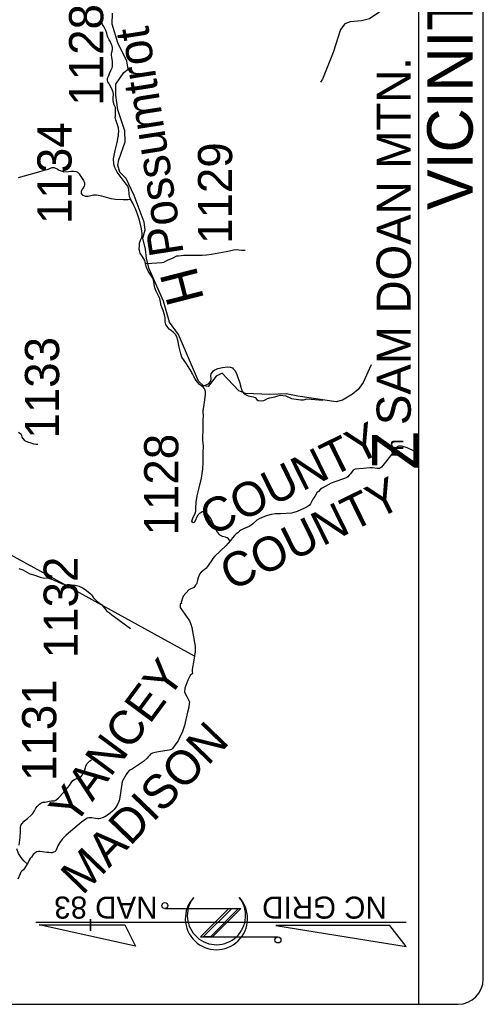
# Model space of a CAD drawing. Extents: x 264770 to 739672, y 157173 to 249791.
# Drawn here: x 727650 to 728336, y 157173 to 158631 of the extents above; entities that cross this region are included whole.
import ezdxf

# ---------------------------------------------------------------- set-up
doc = ezdxf.new("R2010")
doc.units = 0
for name, color, linetype in [('Old_Level_27', 7, 'Continuous'), ('Old_Level_5', 7, 'Continuous'), ('Prop Cable Guiderail Anchor Unit CELL', 7, 'Continuous'), ('Prop Cable Guiderail Single Face', 7, 'Continuous'), ('Prop Dimension', 7, 'Continuous'), ('Prop GRAU 350 Approach CELL', 7, 'Continuous'), ('Prop GRAU M350 Trailing CELL', 7, 'Continuous'), ('Prop Guardrail Anchor Unit CELL', 7, 'Continuous'), ('Prop Lane Arrow Right Turn CELL', 7, 'Continuous'), ('Prop Lane Arrow Shared Lt and Thru CELL', 7, 'Continuous'), ('Prop Structure Anchor Unit CELL', 7, 'Continuous'), ('Prop_centerline', 7, 'Continuous'), ('Scratch_Level_0', 7, 'Continuous'), ('stationing', 7, 'Continuous')]:
    doc.layers.add(name, color=color, linetype=linetype)

msp = doc.modelspace()

# ---------------------------------------------------------------- linework, layer by layer
at = {"layer": 'Old_Level_5'}
for points in [[(728240.9, 158679.5), (728193.4, 158646.2), (728183.1, 158643.1), (728167.9, 158632.5), (728156.2, 158629.4), (728139.4, 158628.3), (728131.5, 158625), (728124.9, 158616.5), (728114.4, 158582.5), (728098.4, 158543.3), (728095.3, 158538.8)], [(728170.6, 158119.7), (728158.6, 158093.8), (728151.3, 158083.6), (728142.9, 158076.3), (728128, 158067.5), (728118.5, 158064.9), (728061.8, 158073.3), (728044.8, 158076.8), (728020.5, 158075.8), (727984.2, 158077.7), (727974.4, 158081.5), (727949.7, 158107.5), (727940.9, 158103.1), (727929.1, 158087.8), (727922.2, 158088.6), (727914.8, 158095.8), (727885.2, 158165.1), (727871.8, 158183.1), (727863, 158214.3), (727841.9, 158262.3), (727837.8, 158277.6), (727836.5, 158291.1), (727832.5, 158307.5), (727835.7, 158319.7), (727834.3, 158331.4), (727819.5, 158371), (727807.4, 158395.9), (727798.4, 158405.6), (727795.4, 158415.6), (727796.7, 158423.7), (727806.4, 158450.2), (727805.8, 158466.6), (727795.2, 158497.8), (727792.4, 158519.5), (727792.5, 158535.8), (727804.1, 158552.9), (727810.8, 158558), (727808.8, 158569.7), (727795.1, 158597), (727786.9, 158624.7), (727787.4, 158641)]]:
    msp.add_lwpolyline(points, dxfattribs=at)
at = {"layer": 'Prop Dimension'}
msp.add_line((727948.2, 157293.8), (727948.2, 157293.8), dxfattribs=at)
at = {"layer": 'Prop GRAU 350 Approach CELL'}
for p, q in [((728240.9, 157172.6), (728240.9, 160226.7)), ((728336.5, 157210.1), (728336.5, 160189.2)), ((726994.9, 157172.6), (728299, 157172.6))]:
    msp.add_line(p, q, dxfattribs=at)
msp.add_arc((728299, 157210.1), 37.5, 270, 360, dxfattribs=at)
at = {"layer": 'Prop Guardrail Anchor Unit CELL'}
msp.add_line((727701.1, 157802.8), (727626.3, 157844), dxfattribs=at)
msp.add_lwpolyline([(727908.8, 157688.5), (727776, 157761.6), (727701.1, 157802.8)], dxfattribs=at)
at = {"layer": 'Prop Lane Arrow Right Turn CELL'}
msp.add_lwpolyline([(727661.1, 157380.5), (727656.8, 157384.6), (727653.8, 157388.1), (727651.1, 157391.7), (727648.3, 157396.2), (727645.6, 157402.7)], dxfattribs=at)
at = {"layer": 'Prop Lane Arrow Shared Lt and Thru CELL'}
for points in [[(727813.9, 158365.6), (727812.6, 158369.5), (727812.3, 158373.4), (727811.5, 158380.1), (727810, 158384.6), (727806.4, 158389.8), (727794.3, 158405.6), (727792, 158410.4), (727791, 158412.3), (727789.6, 158417.3), (727789, 158425.2), (727791.2, 158437.6), (727794.5, 158449.2), (727795.9, 158457.5), (727796.1, 158459.3), (727796.4, 158462.4), (727796.6, 158465.3), (727796.1, 158470.9), (727792.1, 158482.8), (727791.6, 158485), (727791.5, 158486.6), (727791.6, 158488.3), (727791.8, 158491.1), (727791.9, 158494.4), (727791.9, 158498.4), (727791.6, 158501), (727789.9, 158505.1), (727788.7, 158508.8), (727788.3, 158512.2), (727788.3, 158516), (727788.8, 158520.4), (727788.6, 158523.9), (727787.6, 158526.4), (727785.5, 158530.9), (727783.2, 158535.2), (727781.9, 158537.3), (727780.7, 158539), (727780, 158541.3), (727780.1, 158544), (727780.4, 158545.6), (727781.8, 158548.5), (727783.2, 158551.7), (727785.1, 158555.8), (727786.4, 158558.7), (727786.9, 158559.8), (727787.2, 158561.7), (727787.6, 158565.3), (727787.6, 158569.2), (727786.3, 158575.5), (727785.8, 158578.9), (727786, 158581.5), (727786.9, 158584.7), (727787.4, 158587.3), (727787.6, 158590.1), (727787, 158592.5), (727786, 158594.4), (727784.2, 158598.5), (727782.4, 158601.6), (727780.7, 158605.3), (727779.6, 158608.2), (727778.8, 158611.1), (727777.4, 158615.3), (727776.1, 158618.4), (727774.6, 158621.2), (727772.6, 158624.2), (727771.1, 158627.8), (727770.9, 158631), (727771, 158634.3)], [(727648.3, 158397.7), (727678.1, 158406), (727684.8, 158407.8), (727687.9, 158408.6), (727690.7, 158409.2), (727694.7, 158410.8), (727696.5, 158411.8), (727698.1, 158412.3), (727700.6, 158412.3), (727705.4, 158410.4), (727708.6, 158408.5), (727712.9, 158406.7), (727715.5, 158406), (727722.3, 158406.3), (727726.4, 158406.7), (727729.8, 158406.6), (727733.5, 158406.2), (727735.1, 158405.7), (727736.2, 158404.8), (727737.8, 158403.1), (727739.6, 158400.2), (727744.4, 158393), (727744.8, 158391.9), (727745.7, 158389.7), (727745.7, 158386.8), (727745.4, 158384.7), (727743.2, 158380.9), (727741, 158377.2), (727741.1, 158373.9), (727742.5, 158371.7), (727746.9, 158369.9), (727751.2, 158369.9), (727759.4, 158371.6), (727763.9, 158372), (727771.3, 158370.5), (727777.9, 158368.3), (727784.9, 158366.3), (727791.7, 158365.2), (727803, 158364.8), (727810.8, 158365.1), (727813.9, 158365.6)], [(727836.5, 158269.9), (727835.1, 158274.3), (727832.4, 158279.5), (727828.6, 158285.6), (727827.3, 158289.2), (727827.1, 158291), (727827.1, 158292.6), (727827.2, 158295.1), (727827.5, 158300.2), (727828.8, 158304.6), (727830.8, 158308.8), (727831.5, 158311.3), (727831.5, 158314.7), (727830.1, 158321.6), (727827.5, 158334.3), (727824.5, 158343.3), (727821.7, 158350.8), (727818.7, 158356.9), (727817.5, 158359.3), (727813.9, 158365.6)], [(727836.5, 158269.9), (727845.4, 158270.6), (727853.2, 158270.9), (727860.5, 158271.5), (727863.4, 158272.2), (727869, 158274.8), (727877.2, 158278.4), (727882.7, 158281.2), (727885.3, 158281.6), (727892.8, 158282.2), (727904.9, 158282.2), (727920.4, 158282.4), (727926.4, 158282.9), (727933.9, 158284), (727955.8, 158287.7), (727960.8, 158288.7), (727966.6, 158290.1), (727970.7, 158290.6), (727974.7, 158290.3), (727978.2, 158289.8), (727983.8, 158290)], [(727919.5, 158088.5), (727916.1, 158090.6), (727911.5, 158096.7), (727908, 158102.6), (727905.8, 158106.6), (727905.1, 158107.9), (727904.3, 158109.4), (727902.1, 158113.3), (727897.2, 158121.5), (727892.6, 158127.7), (727890.2, 158131.4), (727888.4, 158136), (727886.3, 158146), (727884.2, 158156.7), (727882.5, 158161.2), (727880.7, 158164.7), (727877.1, 158168.4), (727874.6, 158170.3), (727872.7, 158171.6), (727871.5, 158173), (727868.2, 158176.7), (727866.2, 158179.8), (727865.3, 158184), (727865.2, 158189.8), (727864.3, 158194.2), (727862.5, 158200.3), (727859.7, 158207.6), (727858.5, 158213.1), (727857.4, 158218.3), (727855.6, 158222.2), (727851.9, 158229.3), (727850.1, 158234.1), (727849.1, 158239), (727848.5, 158243.6), (727847.2, 158248.1), (727844.1, 158253), (727840.3, 158258.9), (727837.6, 158264.4), (727837.3, 158265.7), (727836.5, 158269.9)], [(727919.5, 158088.5), (727924.8, 158090), (727929.4, 158091.8), (727932.8, 158095.7), (727933.5, 158099.2), (727933, 158104), (727933.6, 158106.6), (727937.2, 158111.1), (727938.9, 158112.3), (727941.2, 158113.7), (727943.6, 158114.7), (727950.5, 158116.1), (727957.7, 158116.9), (727961.6, 158116.7), (727964.9, 158115.4), (727966.3, 158113.9), (727968.5, 158111.5), (727970.8, 158106.9), (727973.2, 158101.3), (727976.1, 158093.2), (727976.9, 158088.5), (727978.2, 158084), (727979.1, 158081.6), (727982.5, 158077), (727988.2, 158073.9), (727990.7, 158073.5), (727995.6, 158072.3), (727998.5, 158071.3), (728000.9, 158068.5), (728003.3, 158067.3), (728007.6, 158066.7), (728011.4, 158067.3), (728013.6, 158068.2), (728016.9, 158070), (728018.7, 158070.5), (728020.4, 158070.9), (728027.6, 158072.3), (728032.2, 158074.1), (728035.6, 158074.8), (728044.3, 158073.9), (728052.7, 158070.1), (728066.2, 158067.9), (728070.4, 158068.1), (728075.6, 158069.8), (728098.7, 158067.8)], [(727961.6, 157858.9), (727960.3, 157860.6), (727959.2, 157862.2), (727957.3, 157863.8), (727954.9, 157864.7), (727950.3, 157865.8), (727947.5, 157866.9), (727946.1, 157868.3), (727942.9, 157871.9), (727937.7, 157882.4), (727932.8, 157892.5), (727928.2, 157898.9), (727926.6, 157900.8), (727924.4, 157901.4), (727922.1, 157902.3), (727920.4, 157902.2), (727915.8, 157899.2), (727913.4, 157896.8), (727908.8, 157887), (727906.9, 157886), (727905.7, 157886.7), (727905, 157888.3), (727905.2, 157889.8), (727906.3, 157892.9), (727909.6, 157900.2), (727910.6, 157903.1), (727910.9, 157908.6), (727911.1, 157916), (727912.8, 157926), (727915.3, 157935.7), (727919, 157952), (727921.2, 157966.1), (727921.7, 157975.6), (727921.8, 157990.8), (727922.1, 157999.3), (727921.4, 158008.2), (727921.4, 158014.2), (727921.5, 158022.4), (727921.8, 158037.3), (727922.3, 158045.4), (727921.8, 158049.4), (727921.8, 158052.5), (727922.8, 158057.6), (727924.2, 158067.9), (727925.2, 158076.5), (727925, 158080.1), (727924.8, 158082.6), (727923.7, 158084.4), (727922, 158086.4), (727919.5, 158088.5)], [(727648.1, 158020.1), (727650, 158018.8), (727651.1, 158017.5), (727652.5, 158015.5), (727653, 158012.8), (727654, 158011.1), (727657.1, 158008), (727661.7, 158005.7), (727666.5, 158004.2), (727670.8, 158002.8), (727673.8, 158002.6), (727676.6, 158002.4)], [(727648.6, 157818.3), (727654.8, 157816), (727664.8, 157810.2), (727672.4, 157808.2), (727680.2, 157805.6), (727684.7, 157804.4), (727692.6, 157803.9), (727698.8, 157801.7), (727705.5, 157799), (727712.7, 157795.3), (727717.3, 157794.4), (727731.9, 157793.6), (727737.9, 157792), (727742.8, 157789.5), (727746.9, 157787.1), (727753.9, 157781.5), (727756.1, 157779.1), (727759.5, 157774.8), (727763.7, 157770.1), (727768, 157767), (727771.4, 157764.2), (727775.8, 157759.5), (727778.4, 157755.6), (727783, 157752.6), (727786.3, 157749.8), (727790, 157747.2), (727814.1, 157729.5)], [(727649.1, 157408.2), (727650.8, 157420.2), (727651.1, 157428.6), (727651.3, 157434.5), (727651.8, 157437.3), (727653.2, 157440.2), (727656.5, 157444), (727662.2, 157448.4), (727666.5, 157452.2), (727669.2, 157455.4), (727671.7, 157459), (727673.9, 157463.2), (727676.5, 157466.3), (727679.2, 157469), (727681.5, 157470.8), (727684.4, 157471.9), (727687.9, 157472.3), (727693.7, 157473.4), (727697.1, 157474), (727701.5, 157474.2), (727703.4, 157475.1), (727707.2, 157478.3), (727715.4, 157487.1), (727721.3, 157493.6), (727723.8, 157496.6), (727726.2, 157500.7), (727728.8, 157504.3), (727731.3, 157505.8), (727734.1, 157506.9), (727737.3, 157507), (727739.4, 157508.3), (727742.5, 157512.2), (727746.3, 157519.8), (727747.9, 157525.2), (727749.4, 157528.6), (727751.6, 157531), (727753.8, 157533.2), (727756.5, 157534.6)]]:
    msp.add_lwpolyline(points, dxfattribs=at)
at = {"layer": 'Prop Structure Anchor Unit CELL'}
for points in [[(728201, 157987.4), (728185.7, 157968.5), (728183, 157966.6), (728179.8, 157966.4), (728172.6, 157967.4), (728168.7, 157967.4), (728159, 157966.6), (728146.7, 157965.4), (728143.7, 157964.1), (728142.1, 157962), (728139.9, 157958.4), (728137.9, 157956.4), (728135.9, 157954.2), (728134.2, 157953.2), (728131.1, 157951.7), (728116.5, 157946.8), (728111.4, 157944.8), (728097.9, 157937.1), (728095.3, 157935.5), (728092.4, 157932.5), (728090, 157930.2), (728087, 157925), (728084.3, 157921), (728080.5, 157914), (728078.7, 157911.6), (728075.8, 157909.4), (728071.7, 157907.7), (728061, 157902.5), (728056, 157901.1), (728052.7, 157900.3), (728036.4, 157899.2), (728029, 157899.2), (728022.4, 157898.3), (728016.8, 157896.9), (728012.3, 157895.4), (728007.9, 157893.3), (728004.8, 157891.7), (728001.3, 157889.7), (727995.4, 157884.6), (727992.6, 157882.2), (727989.8, 157880.3), (727981.2, 157877.1), (727977.6, 157874.9), (727975.5, 157873.3), (727972.8, 157871.1), (727970.7, 157869.4), (727968.1, 157867.1), (727965.3, 157863.8), (727962.3, 157859.7), (727955.3, 157851.9), (727938.9, 157836.7), (727935.9, 157833), (727934.5, 157830.8), (727933.6, 157829), (727930.1, 157824), (727928.3, 157821.4), (727925.6, 157818.2), (727923.3, 157816.1), (727918.6, 157812.6), (727916.2, 157809.9), (727914.5, 157804.6), (727913.2, 157800.9), (727912.2, 157797), (727912.1, 157796.5), (727911.7, 157795.2), (727911, 157794.2), (727910.4, 157793.3), (727908, 157790.1), (727900.4, 157786.8), (727892, 157777), (727889.4, 157769.8), (727889.2, 157768.4), (727889.4, 157766.4), (727887.4, 157765.9), (727887.4, 157760.2), (727901.6, 157740.5), (727903.4, 157735.7), (727904.9, 157730.8), (727906.6, 157722.2), (727910, 157703.4), (727909.8, 157699.2), (727909.9, 157695.4), (727907.8, 157682.5), (727905.5, 157668.5), (727905.5, 157665.5), (727905.8, 157662.5), (727902.6, 157659.5), (727898.8, 157652.6), (727896.2, 157645), (727894.3, 157640.8), (727893.9, 157635.1), (727897.7, 157628.7), (727901.4, 157620.7), (727900.9, 157618.3), (727900.3, 157612.9), (727898.5, 157605.4), (727893.9, 157585.4)], [(728240.9, 157986.5), (728240.8, 157986.6), (728239.9, 157987.5), (728236.5, 157989.9), (728233.1, 157992.4), (728232.2, 157992.8), (728223.9, 157997.2), (728215.8, 157999.6), (728211, 157999.6), (728208.7, 157998.4), (728201, 157987.4)], [(727893.9, 157585.4), (727892.2, 157579.5), (727890.8, 157575.4), (727886.2, 157566.7), (727884.4, 157562.7), (727881.2, 157558.4), (727876.4, 157551.8), (727875, 157550.3), (727873.3, 157549.6), (727871.2, 157549), (727855.5, 157546.8), (727850.4, 157545.8), (727846.6, 157544.6), (727843.7, 157543.1), (727842.1, 157541.4), (727840.4, 157539.2), (727838.9, 157537.3), (727833.2, 157532.4), (727828.8, 157529.2), (727816.8, 157521.6), (727812.3, 157519), (727809.4, 157516.1), (727807.4, 157512.8), (727801.8, 157502.8), (727801.2, 157499.1), (727800.7, 157495.7), (727799.7, 157489.4), (727797.6, 157475.9), (727796.6, 157472.8), (727794.6, 157468.6), (727792.2, 157464.7), (727789.7, 157461.1), (727787.4, 157458.9), (727783.8, 157455.6), (727780, 157453), (727776, 157450.4), (727772, 157448.6), (727769.6, 157447.8), (727767.9, 157447.6), (727765.7, 157447.6), (727762, 157447.7), (727756.9, 157448.9), (727752.4, 157448.9), (727750.1, 157448.4), (727747.8, 157447.1), (727741.5, 157442.3), (727737.8, 157439.6), (727718.6, 157423.2), (727716.8, 157421.3), (727714.9, 157419.4), (727713.4, 157417.8), (727712, 157415.8), (727709.3, 157412.3), (727706.4, 157407.4), (727703.4, 157400), (727702, 157398.5), (727700, 157397.8), (727698.3, 157397.1), (727696.1, 157397.1), (727692.9, 157397.3), (727690, 157397.6), (727680, 157398.8), (727677.9, 157398.8), (727675.5, 157398.3), (727673.1, 157397.1), (727671.9, 157395.9), (727670, 157394.3), (727667.4, 157390.8), (727665.6, 157388.5), (727664.1, 157385.9), (727661.8, 157381.6), (727655.4, 157371.7), (727653.2, 157369.7), (727651.9, 157368.2), (727650.8, 157365.9), (727647.1, 157357.8)]]:
    msp.add_lwpolyline(points, dxfattribs=at)
at = {"layer": 'Prop_centerline'}
for p, q in [((727906.7, 157329.9), (727907.1, 157330.6)), ((727907.1, 157330.6), (727906.7, 157329.9)), ((727864.9, 157314.4), (727977.3, 157314.4)), ((727959.7, 157314.4), (727917.9, 157272.5)), ((727974.2, 157314.4), (727932.4, 157272.5)), ((727974.2, 157314.4), (727932.4, 157272.5)), ((727932.4, 157272.5), (727974.2, 157314.4)), ((727977.3, 157314.4), (727935.4, 157272.5)), ((728222.3, 157293.8), (727673.8, 157293.8)), ((727917.9, 157272.5), (728032.3, 157272.5))]:
    msp.add_line(p, q, dxfattribs=at)
for points in [[(727932.4, 157272.5), (727921.9, 157272.5), (727964.1, 157314.4), (727974.2, 157314.4)], [(727821.3, 157258.7), (727678.9, 157290.1), (727805.5, 157290.1)], [(728029.2, 157289.4), (728222.3, 157258.3), (728198, 157289.4)]]:
    msp.add_lwpolyline(points, close=True, dxfattribs=at)
for centre in [(727864.9, 157318.9), (728032.4, 157268)]:
    msp.add_circle(centre, 4.47, dxfattribs=at)
for centre, radius, start, end in [((727941.3, 157299.6), 46.1, 137.84, 42.3941), ((727941.3, 157304.1), 43.2, 143.095, 38.6287)]:
    msp.add_arc(centre, radius, start, end, dxfattribs=at)
at = {"layer": 'stationing'}
for p, q in [((727754.8, 157295.8), (727754.8, 157298.8)), ((727754.8, 157298.8), (727754.8, 157281.6)), ((727754.8, 157281.6), (727754.8, 157295.8))]:
    msp.add_line(p, q, dxfattribs=at)

# ---------------------------------------------------------------- texts
at = {"layer": 'Old_Level_27'}
msp.add_text('Possumtrot', height=50.62, rotation=98.8717, dxfattribs=at).set_placement((727893.1, 158284.9))
at = {"layer": 'Prop Cable Guiderail Anchor Unit CELL'}
msp.add_text('VICINITY MAP', height=67.5, rotation=90, dxfattribs=at).set_placement((728320.9, 158349.3))
at = {"layer": 'Prop Cable Guiderail Single Face'}
for s, p in [('1128', (727773.7, 158503.8)), ('1134', (727726.8, 158328.6)), ('1129', (727964.6, 158299)), ('1133', (727708.4, 158010.6)), ('1128', (727884.9, 157867.1)), ('1132', (727736, 157685.2)), ('1131', (727704.2, 157503.4))]:
    msp.add_text(s, height=50.62, rotation=90, dxfattribs=at).set_placement(p)
at = {"layer": 'Prop GRAU 350 Approach CELL'}
for s, p in [('NAD 83', (727854, 157332.2)), ('NC GRID', (728193.5, 157332.2))]:
    msp.add_text(s, height=32.66, rotation=180, dxfattribs=at).set_placement(p)
at = {"layer": 'Prop GRAU M350 Trailing CELL'}
msp.add_text('m', height=24.1, rotation=90, dxfattribs=at).set_placement((728218.3, 157983.1))
at = {"layer": 'Prop Guardrail Anchor Unit CELL'}
msp.add_text('H', height=55.1, rotation=284.3732, dxfattribs=at).set_placement((727856.8, 158254.8))
at = {"layer": 'Prop Structure Anchor Unit CELL'}
for s, rotation, p in [('COUNTY', 26.2164, (727933.2, 157865.5)), ('COUNTY', 26.2164, (727963.3, 157784.3)), ('YANCEY', 53.5061, (727730.6, 157435.3)), ('MADISON', 45.9826, (727742.9, 157333))]:
    msp.add_text(s, height=50.62, rotation=rotation, dxfattribs=at).set_placement(p)
at = {"layer": 'Scratch_Level_0'}
for s, height, p in [('SAM DOAN MTN.', 50.625, (728229.1, 158030.6)), ('Z', 68.8, (728240.7, 157964.9))]:
    msp.add_text(s, height=height, rotation=90, dxfattribs=at).set_placement(p)

doc.saveas('drawing.dxf')
